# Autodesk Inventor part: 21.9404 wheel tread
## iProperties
Created: 2010-10
Part Number: 21.9404 wheel tread
Document SubType Name: Modeling
Designer: Administrator
Density: 0.93 g/cm^3
Material: Rubber
Mass: 130.287 g
Surface Area: 306.261 cm^2
Volume: 140.093 cm^3
Author: Administrator
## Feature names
1. Base1
